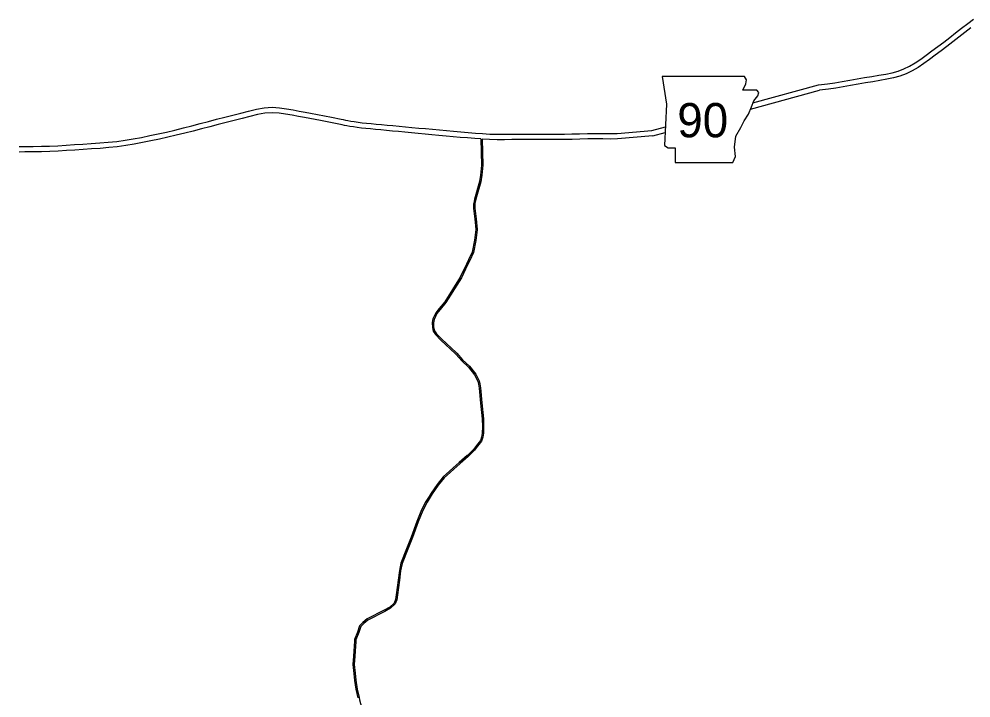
# Model space of a CAD drawing. Extents: x 1574966 to 1597594, y 720505 to 737840.
# Drawn here: x 1575689 to 1584502, y 731317 to 737598 of the extents above; entities that cross this region are included whole.
import ezdxf

# ---------------------------------------------------------------- set-up
doc = ezdxf.new("R2010")
doc.units = 0
for name, color, linetype in [('Level 21', 7, 'Continuous'), ('S_EDGE_PAVEMENT', 7, 'Continuous'), ('S_EDGE_PAVEMENT_AERIAL', 7, 'Continuous')]:
    doc.layers.add(name, color=color, linetype=linetype)

msp = doc.modelspace()

# ---------------------------------------------------------------- linework, layer by layer
at = {"layer": 'Level 21'}
msp.add_lwpolyline([(1581644.7, 737065.7), (1581682.8, 736812), (1581665.9, 736427.1), (1581699.7, 736405.9), (1581763.2, 736405.9), (1581763.2, 736270.6), (1582296.1, 736270.6), (1582321.5, 736325.6), (1582313, 736414.4), (1582325.7, 736515.9), (1582372.2, 736596.3), (1582401.8, 736655.5), (1582444.1, 736718.9), (1582469.5, 736786.6), (1582490.6, 736841.6), (1582528.7, 736888.1), (1582537.2, 736917.7), (1582520.2, 736938.9), (1582389.1, 736938.9), (1582418.7, 736998.1), (1582423, 737036.1), (1582405.4, 737065.4)], close=True, dxfattribs=at)
at = {"layer": 'S_EDGE_PAVEMENT'}
for p, q in [((1582483.7, 736823.5), (1583091, 736990.2)), ((1582461.6, 736765.6), (1583100.4, 736940.9)), ((1581548, 736566.7), (1581673.5, 736601.2)), ((1581556.8, 736517.3), (1581671.2, 736548.7))]:
    msp.add_line(p, q, dxfattribs=at)
at = {"layer": 'S_EDGE_PAVEMENT_AERIAL'}
for points in [[(1583091, 736990.2), (1583175.6, 736999.5), (1583243.2, 737009.4), (1583311.3, 737020.6), (1583379.8, 737032.6), (1583448.8, 737044.8), (1583517.8, 737056.6), (1583585.1, 737068.3), (1583650.6, 737079.3), (1583713.1, 737089.9), (1583772.2, 737102), (1583828.3, 737117.5), (1583882.1, 737137.8), (1583934.4, 737163.7), (1583985.9, 737193.8), (1584037.2, 737227.7), (1584088.8, 737264.6), (1584141.4, 737303.7), (1584195.3, 737344), (1584250.1, 737385.4), (1584305.4, 737427.7), (1584360.5, 737470.3), (1584416.1, 737513.2), (1584472, 737555.8)], [(1584502.3, 737516), (1584446.5, 737473.5), (1584391.1, 737430.8), (1584335.9, 737388), (1584280.4, 737345.6), (1584225.4, 737304), (1584171.3, 737263.6), (1584118.2, 737224.2), (1584065.5, 737186.4), (1584012.3, 737151.4), (1583958.1, 737119.6), (1583902.1, 737091.9), (1583843.8, 737069.9), (1583783.9, 737053.3), (1583722.3, 737040.8), (1583659, 737030), (1583593.5, 737019), (1583526.3, 737007.3), (1583457.4, 736995.5), (1583388.5, 736983.3), (1583319.6, 736971.3), (1583250.9, 736960), (1583182, 736949.9), (1583100.4, 736940.9)], [(1584471.9, 737555.7), (1584527.3, 737598.3)], [(1575688.8, 736418.3), (1575742.4, 736418.7), (1575819.8, 736419.7), (1575896.1, 736421.3), (1575971.9, 736423.2), (1576047.9, 736426.4), (1576124.2, 736431), (1576201, 736436.3), (1576278.6, 736441.8), (1576357.1, 736446.9), (1576435.9, 736452), (1576514.7, 736458.5), (1576593.2, 736466.2), (1576670.5, 736476.4), (1576747, 736489.2), (1576823.4, 736503.9), (1576900.4, 736519.9), (1576977.9, 736535.9), (1577055.4, 736552.8), (1577132.7, 736571.3), (1577210.2, 736590.7), (1577287.5, 736610.7), (1577364.8, 736630.9), (1577441.9, 736650.9), (1577518.6, 736670.8), (1577594.8, 736690.5), (1577669.7, 736709.4), (1577742.7, 736728), (1577814.3, 736746.2), (1577885.9, 736763.2), (1577958.5, 736776.9), (1578031.5, 736781.7), (1578101, 736777.7), (1578165.3, 736768.2), (1578226, 736757.7), (1578283.7, 736747.2), (1578338.9, 736737.6), (1578386.2, 736728.8), (1578582.6, 736690.6)], [(1578478.8, 736660.7), (1578330.4, 736688.3), (1578274.9, 736698), (1578217.2, 736708.5), (1578157.4, 736718.9), (1578095.9, 736728), (1578031.7, 736731.6), (1577964.9, 736727.2), (1577896.3, 736714.3), (1577826.2, 736697.6), (1577755.1, 736679.5), (1577681.9, 736660.9), (1577607.2, 736642.1), (1577531.1, 736622.4), (1577454.4, 736602.5), (1577377.4, 736582.5), (1577300.1, 736562.3), (1577222.5, 736542.3), (1577144.6, 736522.7), (1577066.5, 736504), (1576988.3, 736487), (1576910.5, 736470.9), (1576833.2, 736454.9), (1576755.9, 736440), (1576678, 736426.9), (1576598.9, 736416.5), (1576519.2, 736408.7), (1576439.6, 736402.1), (1576360.3, 736397), (1576282, 736391.9), (1576204.5, 736386.5), (1576127.5, 736381.1), (1576050.5, 736376.5), (1575973.6, 736373.2), (1575897.2, 736371.3), (1575820.6, 736369.8), (1575742.9, 736368.7), (1575689.3, 736368.3)], [(1579965.1, 736489.1), (1579910.4, 736492.9), (1579842.5, 736498), (1579774.4, 736503.6), (1579708.1, 736509.8), (1579642, 736516), (1579576.5, 736522.2), (1579511.6, 736528.4), (1579447.5, 736534.5), (1579384.1, 736540.5), (1579322.1, 736546.4), (1579261.6, 736551.6), (1579202.8, 736556.8), (1579146, 736562.3), (1579091.7, 736567.6), (1579039.9, 736572.5), (1578990.7, 736577), (1578944, 736581.1), (1578900, 736585.5), (1578858.9, 736589.9), (1578820.7, 736594.7), (1578785.2, 736599.8), (1578752.8, 736605), (1578724.7, 736610.5), (1578700.7, 736615), (1578679.8, 736619.4), (1578665.4, 736622.6), (1578480.5, 736660.4)], [(1578582.6, 736690.6), (1578670.8, 736672.7), (1578690.4, 736668.2), (1578710.4, 736664.1), (1578734.1, 736659.6), (1578761.6, 736654.2), (1578792.7, 736649.2), (1578827.3, 736644.3), (1578864.8, 736639.6), (1578905.2, 736635.2), (1578948.6, 736630.9), (1578995.1, 736626.8), (1579044.5, 736622.3), (1579096.5, 736617.4), (1579150.9, 736612.1), (1579207.4, 736606.5), (1579266, 736601.4), (1579326.6, 736596.2), (1579388.9, 736590.3), (1579452.2, 736584.3), (1579516.4, 736578.2), (1579581.2, 736571.9), (1579646.7, 736565.8), (1579712.8, 736559.6), (1579778.8, 736553.4), (1579846.4, 736547.9), (1579914.1, 736542.8), (1579981.3, 736538), (1580047.7, 736534.3), (1580115, 736532.2), (1580182.5, 736532.3), (1580250.9, 736532.8), (1580319.7, 736533.6), (1580389, 736534.4), (1580458.5, 736534.8), (1580528.1, 736534.8), (1580597.8, 736534.7), (1580667.7, 736534.5), (1580737.9, 736534.8), (1580808.5, 736535.3), (1580879, 736536.3), (1580953, 736539.6), (1581024.6, 736540.3), (1581095.1, 736540.1), (1581161.2, 736538.3), (1581227.3, 736539.9), (1581548, 736566.7)], [(1579965.1, 736489.1), (1579971.2, 736247.9), (1579961.6, 736154.6), (1579952.1, 736095.9), (1579905.4, 735933.1), (1579898.2, 735893.6), (1579897.9, 735887.4)], [(1579977.1, 736488.2), (1579983.2, 736247.5), (1579973.5, 736153), (1579963.8, 736093.3), (1579917.1, 735930.4), (1579910.2, 735892.2), (1579909.9, 735886.8)], [(1579977.1, 736488.2), (1579983.2, 736247.5), (1579973.5, 736153), (1579963.8, 736093.3), (1579917.1, 735930.4), (1579910.2, 735892.2), (1579909.9, 735886.8)], [(1581556.8, 736517.3), (1581230, 736489.9), (1581161.2, 736488.3), (1581094.4, 736490.1), (1581024.8, 736490.3), (1580954.4, 736489.6), (1580880.4, 736486.3), (1580809, 736485.3), (1580738.2, 736484.8), (1580667.8, 736484.5), (1580597.7, 736484.7), (1580528, 736484.8), (1580458.6, 736484.8), (1580389.4, 736484.4), (1580320.3, 736483.6), (1580251.4, 736482.8), (1580182.7, 736482.3), (1580114.3, 736482.2), (1580045.6, 736484.4), (1579978.1, 736488.1), (1579977.1, 736488.2)], [(1579897.9, 735887.4), (1579895.9, 735846.9), (1579909, 735748.8), (1579917.4, 735651.8), (1579906.6, 735551.3), (1579883.9, 735441.1), (1579850.5, 735371.2)], [(1579909.9, 735886.8), (1579907.9, 735847.4), (1579920.9, 735750.1), (1579929.4, 735651.7), (1579918.5, 735549.4), (1579895.4, 735437.3), (1579861.3, 735366)], [(1579909.9, 735886.8), (1579907.9, 735847.4), (1579920.9, 735750.1), (1579929.4, 735651.7), (1579918.5, 735549.4), (1579895.4, 735437.3), (1579861.3, 735366)], [(1579850.5, 735371.2), (1579831.3, 735331), (1579773.9, 735211.3), (1579630.3, 734982.7), (1579579.8, 734919.7)], [(1579861.3, 735366), (1579842.1, 735325.8), (1579784.4, 735205.5), (1579640.1, 734975.7), (1579589.2, 734912.1)], [(1579861.3, 735366), (1579842.1, 735325.8), (1579784.4, 735205.5), (1579640.1, 734975.7), (1579589.2, 734912.1)], [(1579579.8, 734919.6), (1579547.8, 734879.7), (1579520.3, 734823.5), (1579514.3, 734789.9), (1579515.5, 734745.7), (1579522.7, 734709.7), (1579545.4, 734678.6), (1579594.4, 734628.5), (1579727.2, 734504), (1579732.9, 734497.6)], [(1579589.2, 734912.1), (1579558, 734873.3), (1579531.8, 734819.7), (1579526.3, 734789), (1579527.5, 734747), (1579533.9, 734714.7), (1579554.6, 734686.4), (1579602.8, 734637.1), (1579735.8, 734512.4), (1579741.9, 734505.6)], [(1579589.2, 734912.1), (1579558, 734873.3), (1579531.8, 734819.7), (1579526.3, 734789), (1579527.5, 734747), (1579533.9, 734714.7), (1579554.6, 734686.4), (1579602.8, 734637.1), (1579735.8, 734512.4), (1579741.9, 734505.6)], [(1579732.9, 734497.6), (1579787, 734437), (1579849.2, 734378.3), (1579906.6, 734306.5), (1579936.5, 734247.9), (1579943.1, 734221.4), (1579948.1, 734184.7), (1579962.1, 734045.1)], [(1579741.9, 734505.6), (1579795.6, 734445.4), (1579858.1, 734386.5), (1579916.8, 734313.1), (1579947.8, 734252.1), (1579954.9, 734223.6), (1579960, 734186.1), (1579974.1, 734046.3)], [(1579741.9, 734505.6), (1579795.6, 734445.4), (1579858.1, 734386.5), (1579916.8, 734313.1), (1579947.8, 734252.1), (1579954.9, 734223.6), (1579960, 734186.1), (1579974.1, 734046.3)], [(1579962.1, 734045.1), (1579976.1, 733899.4), (1579978.4, 733829.2), (1579977.6, 733766.8), (1579971.8, 733731.3), (1579960.2, 733698.7), (1579924.3, 733653.2), (1579896, 733616.4), (1579844.5, 733564.9)], [(1579974.1, 734046.3), (1579988.1, 733900.2), (1579990.4, 733829.3), (1579989.6, 733765.8), (1579983.5, 733728.4), (1579970.9, 733692.8), (1579933.8, 733645.9), (1579905, 733608.5), (1579853, 733556.4)], [(1579844.5, 733564.9), (1579839.1, 733559.5), (1579764.6, 733494.8), (1579615.8, 733362.3), (1579558.9, 733292.8), (1579505.1, 733211.6), (1579486.4, 733181.8)], [(1579853, 733556.4), (1579847.3, 733550.7), (1579772.5, 733485.8), (1579624.4, 733354), (1579568.5, 733285.6), (1579515.2, 733205.1), (1579496.5, 733175.4)], [(1579486.4, 733181.8), (1579456.7, 733134.6), (1579416.6, 733057.7), (1579372.4, 732950.1), (1579320.8, 732805.8), (1579277.7, 732698.1)], [(1579496.5, 733175.4), (1579467.1, 733128.6), (1579427.5, 733052.6), (1579383.6, 732945.8), (1579332, 732801.5), (1579288.9, 732693.7)], [(1579277.7, 732698.1), (1579223.8, 732563.3), (1579210.2, 732495.8), (1579198.6, 732407.3), (1579181.7, 732272.3), (1579174.3, 732228.1), (1579160.6, 732195.4)], [(1579288.9, 732693.7), (1579235.4, 732559.9), (1579222, 732493.9), (1579210.5, 732405.7), (1579193.6, 732270.6), (1579185.9, 732224.8), (1579170.7, 732188.3)], [(1579160.6, 732195.4), (1579120.6, 732158.5), (1579069, 732128.9), (1578913.1, 732047.8), (1578872, 732016.1), (1578842.5, 731983.4), (1578822.1, 731925.5), (1578796.1, 731857.9), (1578794.8, 731841)], [(1579170.7, 732188.3), (1579127.7, 732148.7), (1579074.7, 732118.4), (1578919.5, 732037.6), (1578880.2, 732007.3), (1578853, 731977.2), (1578833.4, 731921.4), (1578807.9, 731855.3), (1578806.8, 731840.2)], [(1578794.8, 731841), (1578784.8, 731704.5), (1578780.3, 731625.2), (1578787.7, 731544), (1578795.1, 731479.7), (1578806.7, 731397.5), (1578825, 731317.2)], [(1578806.8, 731840.2), (1578796.8, 731703.7), (1578792.4, 731625.4), (1578799.6, 731545.2), (1578807, 731481.2), (1578818.5, 731399.6), (1578836.7, 731319.9)], [(1578836.7, 731319.9), (1578841.5, 731299), (1578868.7, 731197.4), (1578884.5, 731148), (1578889.5, 731129.5), (1578894.6, 731096.4), (1578892.3, 731067.1), (1578885.7, 731028.2), (1578872.4, 730997.3), (1578851.7, 730951.5), (1578818, 730909.2), (1578782.4, 730868.1), (1578751.3, 730832.7)]]:
    msp.add_lwpolyline(points, dxfattribs=at)

# ---------------------------------------------------------------- texts
at = {"layer": 'Level 21'}
msp.add_text('90', height=316.8, dxfattribs=at).set_placement((1581783.2, 736504.4))

doc.saveas('drawing.dxf')
